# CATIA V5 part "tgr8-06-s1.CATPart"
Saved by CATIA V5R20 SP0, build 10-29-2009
Part number: TGR8-06-S1
Revision: 5
Definition: design
Nomenclature: TGR8-06-S1
Source: made
Description: NOT SPECIFIED
Bounding box of the stored display mesh (mm): x -4 to 4, y -8 to 0, z -22 to 0.6
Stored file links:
  C:\Users\Raffaele\Desktop\3D X SITO CF\I-MOLD\TGR-S1\tgr8-s1.step\tgr8-06-s1.CATPart
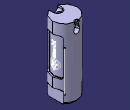
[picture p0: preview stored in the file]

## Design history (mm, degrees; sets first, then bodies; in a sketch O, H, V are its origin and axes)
Set1
  DatumCurve1 "COMPOSITE_CURVE #4318"
  DatumCurve2 "COMPOSITE_CURVE #4365"
  DatumCurve3 "COMPOSITE_CURVE #4598"
  DatumCurve4 "COMPOSITE_CURVE #4658"
  DatumCurve5 "COMPOSITE_CURVE #4710"
  DatumCurve6 "COMPOSITE_CURVE #4871"
  DatumCurve7 "COMPOSITE_CURVE #4898"
  DatumCurve8 "COMPOSITE_CURVE #4925"
  DatumCurve9 "COMPOSITE_CURVE #5011"
  DatumCurve10 "COMPOSITE_CURVE #5050"
  Line1 "LINE #5054": stored without definition
  DatumSurface1 "OPEN_SHELL #4145"
  DatumSurface2 "OPEN_SHELL #4242"
Body1 "MANIFOLD_SOLID_BREP #4243" (main body)
  Solid1: solid without history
